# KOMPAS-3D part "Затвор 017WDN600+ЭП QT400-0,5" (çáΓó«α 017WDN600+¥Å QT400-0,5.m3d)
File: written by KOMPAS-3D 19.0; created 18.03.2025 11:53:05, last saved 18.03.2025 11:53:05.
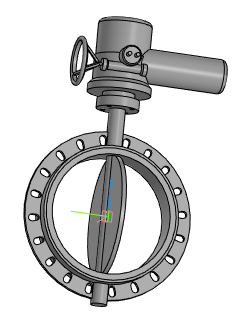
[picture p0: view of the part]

Document properties: Полное имя файла: Затвор 017WDN600+ЭП QT400-0,5.a3d

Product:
- Part/product: Затвор 017WDN600+ЭП QT400-0,5
    Масса: 458.556

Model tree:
1. Операция без истории:1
